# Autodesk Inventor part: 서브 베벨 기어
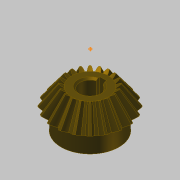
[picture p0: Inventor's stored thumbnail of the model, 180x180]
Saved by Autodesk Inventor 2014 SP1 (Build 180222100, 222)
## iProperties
Created: 2016-04
Part Number: 서브 베벨 기어
Material: 강철, 탄소
Document SubType Name: Modeling
Designer: mdu
Categories: <?xml version="1.0" encoding="UTF-16"?> <MemberInstance><Categories><FamilyTemplate><FamilyTemplateParameter ValueType="xs:double" Id="1" ObjectReferenceKey="da
Mass: 135.037 g
Surface Area: 63.6518 cm^2
Volume: 17.1585 cm^3
Density: 7.87 g/cm^3
Appearance: 얼룩무늬
Author: mdu
Revision Number: 1
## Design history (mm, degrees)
node "맨 위 점"
node "메쉬 평면2"
sketch "톱니 본체 스케치"
  geometry: L1 (0, 0)-(18.003, -31.331); L2 (18.003, -31.331)-(21.664, -28.891); L3 (21.664, -28.891)-(0, 0); L4 (20, -30)-(0, 0); L5 (10.813, -18.818)-(13.012, -17.352); L6 (18.003, -31.331)-(10.813, -18.818); L7 (21.664, -28.891)-(13.012, -17.352); L8 (0, -39.387)-(0, 6.564) reference; L9 (0, -30)-(21.664, -30)
  constraints: 16 end point, 4 point on line, 3 perpendicular, 2 collinear, 1 horizontal alignment, 1 vertical alignment
  dimensions: "d0" = 40 diameter of L4.start L8 (= da_de); "d1" = 36.00616 diameter of L1.end L8 (= da_dfe); "d2" = 43.3282 diameter of L2.end L8 (= da_dae); "d3" = 14.4 distance between parallel lines of L2 L5 (= da_b); "d4" = 28.8906 vertical distance of L2.end L1.start (= da_ve)
revolve "톱니 본체" sketch "톱니 본체 스케치" stored, may be unused: angle "d5" = 90 deg
node "시작점"
node "톱니 평면"
sketch "시작 스케치"
  geometry: L1 (0, -23.505)-(0, 10.645) reference; L2 (-0.834, -2.928)-(0.834, -2.928); A1 r 8.898 centre (-9.698, -3.713) between (-0.834, -2.928) and (-3.903, 3.04); A2 r 8.898 centre (9.698, -3.713) between (3.903, 3.04) and (0.834, -2.928); A3 r 27.357 centre (0, -24.037) between (3.903, 3.04) and (-3.903, 3.04); 1 further point
  constraints: 6 point on circle, 3 centre point, 3 symmetric about line, 2 end point, 1 coincident, 1 perpendicular, 1 other
  dimensions: "d7" = 8.89846 radius of A1 (= fd_rr); "d8" = 9.69794 horizontal distance of point (0, -24.037) A1.centre (= fd_x); "d9" = 20.32439 vertical distance of point (0, -24.037) A1.centre (= fd_y); "d57" = 27.35701 radius of A3 (= 0.5 x fd_dva + 0.3 x da_he); "d58" = 21.10901 distance from line of A3.centre L2 (= 0.5 x fd_dva - 1.12 x da_he)
node "끝점"
  node "끝 평면"
sketch "3D 스케치 오른쪽"
  node "Helical Curve Right" dims "d65" = 229.90621 (computed from da_dm, da_delta, da_beta), "d66" = 31.5, "d67" = 40 (= da_de), "d68" = -5.88003 (= -da_delta), "d69" = 12.16458 (computed from fd_loft, da_delta)
node "끝 평면 오른쪽"
sketch "끝 스케치 오른쪽"
  geometry: L1 (0, -22.649)-(0, 12.15) reference; L2 (-0.497, -1.72)-(0.497, -1.72); A1 r 5.299 centre (-5.775, -2.187) between (-0.497, -1.72) and (-2.324, 1.834); A2 r 5.299 centre (5.775, -2.187) between (2.324, 1.834) and (0.497, -1.72); A3 r 16.291 centre (0, -14.29) between (2.324, 1.834) and (-2.324, 1.834); 1 further point
  constraints: 6 point on circle, 3 centre point, 3 symmetric about line, 2 end point, 1 coincident, 1 perpendicular, 1 other
  dimensions: "d70" = 5.77526 horizontal distance of A3.centre A1.centre (computed from fd_x, fd_ratio); "d71" = 12.10346 vertical distance of point (0, -14.29) A1.centre (computed from fd_y, fd_ratio); "d72" = 5.29916 radius of A1 (computed from fd_rr, fd_ratio); "d73" = 12.57071 distance from line of point (0, -14.29) L2 (computed from d58, fd_ratio); "d74" = 16.29149 radius of A3 (computed from d57, fd_ratio)
feature "로프트 오른쪽" sketch "끝 스케치 오른쪽" dims "d75" = 0, "d77" = 0, "d79" = 0, "d80" = 90 deg, "d85" = 20, "d92" = 90 deg, "d93" = 90 deg, "da_teethtype" = 0 [user parameter]
sketch "3D 스케치 왼쪽"
  node "Helical Curve Left" dims "d26" = 229.90621 (computed from da_dm, da_delta, da_beta), "d27" = 12.16458 (computed from fd_loft, da_delta), "d28" = 40 (= da_de), "d29" = -5.88003 (= -da_delta)
node "끝 평면 왼쪽"
sketch "끝 스케치 왼쪽" dims "d56" = 10.82768 (derived)
  geometry: L1 (0, -35.087)-(0, 18.089) reference; L2 (-0.497, -1.716)-(0.497, -1.716); A1 r 5.299 centre (-5.775, -2.183) between (-0.497, -1.716) and (-2.324, 1.838); A2 r 5.299 centre (5.775, -2.183) between (2.324, 1.838) and (0.497, -1.716); A3 r 16.291 centre (0, -14.287) between (2.324, 1.838) and (-2.324, 1.838); 2 further points; 1 other entity
  constraints: 6 point on circle, 3 centre point, 3 symmetric about line, 2 end point, 1 coincident, 2 other
  dimensions: "d30" = 5.29916 radius of A1 (computed from fd_rr, fd_ratio); "d31" = 5.77526 horizontal distance of point (0, -14.287) A1.centre (computed from fd_x, fd_ratio); "d32" = 12.10346 vertical distance of A1.centre point (0, -14.287) (computed from fd_y, fd_ratio); "d61" = 16.29149 radius of A3 (computed from d57, fd_ratio); "d62" = 12.57071 distance from line of point (0, -14.287) L2 (computed from d58, fd_ratio)
feature "로프트 왼쪽" sketch "끝 스케치 왼쪽" dims "d35" = 0, "d37" = 0, "d39" = 0, "d40" = 90 deg, "d84" = 10, "d90" = 90 deg, "d91" = 90 deg, "da_teethtype" = 0 [user parameter]
sketch "본체 스케치"
  geometry: L1 (0, -35.038)-(0, -19.531) reference; L2 (18.003, -31.331)-(10.813, -18.818) reference; L3 (10.813, -18.818)-(0, -18.818); L4 (18.003, -31.331)-(0, -31.331)
  constraints: 4 end point, 2 perpendicular, 2 point on line
revolve "본체 고정" sketch "본체 스케치" stored, may be unused: angle "d46" = 90 deg
feature "피치 지름" dims angle "d47" = 90 deg
sketch "스케치8"
  geometry: C1 r 17 at (0, 0); 1 further point
  constraints: 1 centre point, 1 coincident
  dimensions: "d94" = 34 diameter of C1
extrude "돌출1" join sketch "스케치8" distance "d95" = 10; taper "d96" = 0 deg
sketch "스케치9"
  geometry: 1 further point
hole "구멍1" sketch "스케치9" at (0, 0) diameter "d97" = 12; stored, may be unused: countersink angle "d101" = 90 deg, drill point angle "d103" = 118 deg; dims "d98" = 6, "d99" = 4, "d100" = 2, "d102" = 8
sketch "스케치10"
  geometry: 1 further point
sketch "스케치11"
  geometry: 1 further point
sketch "스케치12"
  geometry: L1 (-2, 5.657)-(-2, 7.8); L2 (-2, 7.8)-(2, 7.8); L3 (2, 7.8)-(2, 5.657); A1 r 6 centre (0, 0) between (-2, 5.657) and (2, 5.657) reference; 1 further point
  constraints: 6 end point, 2 parallel, 2 point on circle, 1 perpendicular, 1 vertical
  dimensions: "d104" = 4 distance of L1.end L2.end; "d105" = 13.8 dimension on A1 L2
extrude "돌출2" cut sketch "스케치12" stored distance "d106" = 7; taper "d107" = 0 deg
chamfer "모따기1" distance "d108" = 1; stored, may be unused: second distance "d109" = 2, angle "d110" = 45 deg
body "Solid1"
feature "로프트" dims "d17" = 0, "d18" = 90 deg, "d19" = 0, "d20" = 90 deg, "d89" = 0, "da_teethtype" = 0 [user parameter]
pattern_circular "원형 패턴" dims angle "d22" = 360 deg, "d88" = 0, "da_teethtype" = 0 [user parameter]
pattern_circular "원형 패턴 오른쪽" dims angle "d82" = 360 deg, "da_teethtype" = 0 [user parameter]
pattern_circular "원형 패턴 왼쪽" dims angle "d42" = 360 deg, "da_teethtype" = 0 [user parameter]
sketch "끝 스케치"
  geometry: L1 (0, -15.359)-(0, 6.983) reference; L2 (-0.497, -1.72)-(0.497, -1.72); A1 r 5.299 centre (-5.775, -2.187) between (-0.497, -1.72) and (-2.324, 1.834); A2 r 5.299 centre (5.775, -2.187) between (2.324, 1.834) and (0.497, -1.72); A3 r 16.291 centre (0, -14.29) between (2.324, 1.834) and (-2.324, 1.834); 1 further point
  constraints: 6 point on circle, 3 centre point, 3 symmetric about line, 2 end point, 1 coincident, 1 other
  dimensions: "d12" = 5.29916 radius of A1 (computed from fd_rr, fd_ratio); "d15" = 5.77526 horizontal distance of A1.centre point (0, -14.29) (computed from fd_x, fd_ratio); "d16" = 12.10346 vertical distance of A1.centre point (0, -14.29) (computed from fd_y, fd_ratio); "d59" = 16.29149 radius of A3 (computed from d57, fd_ratio); "d60" = 12.57071 distance from line of A3.centre L2 (computed from d58, fd_ratio)
sketch "Sketch6"
  geometry: L1 (20, -30)-(0, 0) reference; L2 (0, -37.8)-(0, 6.3) reference
body "Srf1"
other parameters: "da_b" = 14.4 [user parameter; used in 2 equation terms], "da_de" = 40 [user parameter; used in 4 equation terms], "da_dae" = 43.3282 [user parameter; used in 2 equation terms], "da_dfe" = 36.00616 [user parameter; used in 1 equation term], "da_le" = 36.05551 [user parameter; used in 1 equation term], "da_omega" = 90 deg [user parameter; used in 1 equation term], "da_beta" = 0 [user parameter; used in 2 equation terms], "da_delta" = 5.88003 [user parameter; used in 8 equation terms], "da_alpha" = 20 deg [user parameter; used in 2 equation terms], "da_he" = 4.4 [user parameter; used in 4 equation terms], "da_ve" = 28.8906 [user parameter; used in 1 equation term], "fd_dv" = 48.07402 (computed from da_de, da_delta) [user parameter; used in 1 equation term], "fd_dva" = 52.07402 (computed from da_dae, da_delta) [user parameter; used in 3 equation terms], "fd_dvb" = 45.1748 (computed from fd_dv, da_alpha) [user parameter; used in 2 equation terms], "da_zv" = 240.37008 [user parameter; used in 1 equation term], "fd_loft" = 14.62 (= da_b + 0.05 x da_he) [user parameter; used in 4 equation terms], "fd_ratio" = 5.95514 (computed from da_le, fd_loft) [user parameter; used in 15 equation terms], "fd_rr" = 8.89846 (computed from fd_dd, fd_dvb) [user parameter; used in 6 equation terms], "fd_angle" = 0.66075 (computed from da_zv) [user parameter; used in 4 equation terms], "fd_x1" = 1.58709 (computed from da_dvw, fd_angle) [user parameter; used in 1 equation term], "fd_y1" = 23.98456 (computed from da_dvw, fd_angle) [user parameter; used in 1 equation term], "fd_x2" = 8.11084 (computed from fd_rr, fd_angle2, fd_angle) [user parameter; used in 1 equation term], "fd_y2" = 3.66016 (computed from fd_rr, fd_angle2, fd_angle) [user parameter; used in 1 equation term], "fd_x" = 9.69794 (= fd_x1 + fd_x2) [user parameter; used in 4 equation terms], "fd_y" = 20.32439 (= fd_y1 - fd_y2) [user parameter; used in 4 equation terms], "fd_angle2" = 3.57832 (computed from fd_dvb, fd_dd, da_alpha) [user parameter; used in 2 equation terms], "fd_dd" = 48.55402 (= fd_dva - 0.8 x da_he) [user parameter; used in 2 equation terms], "da_dvw" = 48.07402 [user parameter; used in 2 equation terms], "d11" = 14.62 (= fd_loft), "da_dm" = 32.01232 [user parameter; used in 2 equation terms], "da_x" = 0 [user parameter], "da_m" = 2 [user parameter], "d48" = 0, "d49" = 0, "d50" = 90 deg (= da_omega), "d51" = 9 deg (computed from da_z), "d52" = 0, "d53" = 0, "d54" = 0
